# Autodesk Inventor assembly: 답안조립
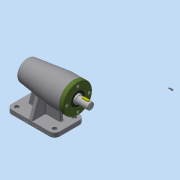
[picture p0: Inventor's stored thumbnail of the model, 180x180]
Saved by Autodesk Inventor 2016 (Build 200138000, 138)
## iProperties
Created: 2018-09
Part Number: 답안조립
Material: 일반
Document SubType Name: Assembly
Designer: 605-11
Author: 605-11
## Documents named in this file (12)
- C:\Users\605-11\Desktop\480907V1033\답안조립.iam
- C:\Users\605-11\Desktop\480907V1033\V벨트풀리.ipt
- C:\Users\605-11\Desktop\480907V1033\멈춤나사 M3.ipt
- C:\Users\605-11\Desktop\480907V1033\베어링 6004.ipt
- C:\Users\605-11\Desktop\480907V1033\베어링 51202.ipt
- C:\Users\605-11\Desktop\480907V1033\본체.ipt
- C:\Users\605-11\Desktop\480907V1033\볼트 M4.ipt
- C:\Users\605-11\Desktop\480907V1033\어댑터슬리브.ipt
- C:\Users\605-11\Desktop\480907V1033\오일 실.ipt
- C:\Users\605-11\Desktop\480907V1033\축.ipt
- C:\Users\605-11\Desktop\480907V1033\커버.ipt
- C:\Users\605-11\Desktop\480907V1033\키 5 x 5 x 16.ipt
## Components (1 placed, 1 different names)
1. V벨트풀리:1 — 각도:1
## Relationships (1: Angle 1)
- 각도:1 [Angle]: V벨트풀리:1
